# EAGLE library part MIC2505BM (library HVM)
MICREL high-side switch
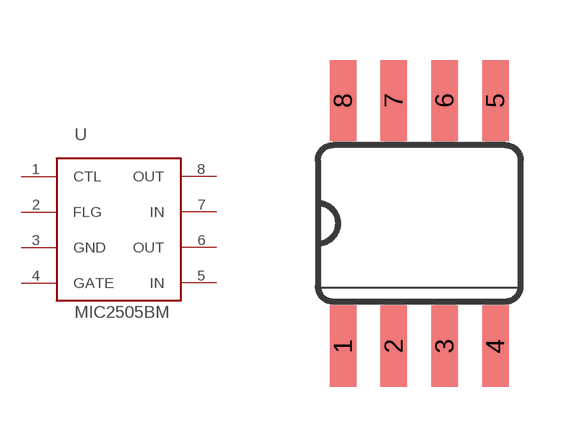
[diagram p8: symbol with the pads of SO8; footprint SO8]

Designator prefix U

## MIC2505BM  [SO8]
1  CTL  pas
2  FLG  pas
3  GND  pas
4  GATE  pas
5  IN  pas
6  OUT  pas
7  IN  pas
8  OUT  pas

## Footprint SO8 (pad centres in mm)
SO8 PACKAGE
smd 0.66 x 2.032: 1 -1.905,-3.073; 2 -0.635,-3.073; 3 0.635,-3.073; 4 1.905,-3.073; 5 1.905,3.073; 6 0.635,3.073; 7 -0.635,3.073; 8 -1.905,3.073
